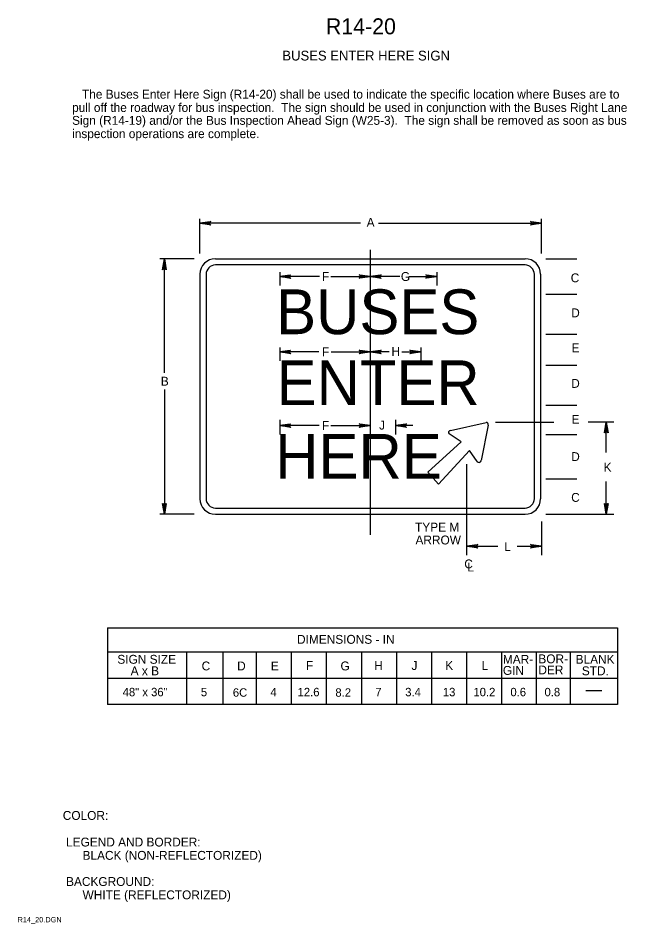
# Model space of a CAD drawing. Extents: x 0.013 to 0.184, y 0.004 to 0.259.
import ezdxf

# ---------------------------------------------------------------- set-up
doc = ezdxf.new("R2010")
doc.units = 0
for name, color, linetype in [('1', 7, 'Continuous'), ('11', 7, 'Continuous'), ('12', 7, 'Continuous'), ('3', 7, 'Continuous')]:
    doc.layers.add(name, color=color, linetype=linetype)

# ---------------------------------------------------------------- blocks, each defined once
blk = doc.blocks.new('RARROW')
at = {"layer": '3'}
for p, q in [((-2.156, 0.28500000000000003), (-2.2665, 0.384625)), ((-2.2665, 0.384625), (0, 0)), ((0, 0), (-2.2665, -0.379125)), ((-2.156, 0.28500000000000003), (-2.075625, 0.12075)), ((0, 0), (-2.156, 0.28500000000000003)), ((-2.14975, -0.2705), (0, 0)), ((-2.075625, 0.12075), (0, 0)), ((0, 0), (-2.074, -0.108)), ((-2.2665, -0.379125), (-2.14975, -0.2705)), ((-2.074, -0.108), (-2.14975, -0.2705))]:
    blk.add_line(p, q, dxfattribs=at)

msp = doc.modelspace()

# ---------------------------------------------------------------- linework, layer by layer
at = {"layer": '11'}
for p, q in [((0.068125, 0.19137500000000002), (0.155375, 0.19137500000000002)), ((0.06375, 0.187), (0.06375, 0.12375)), ((0.15975, 0.187), (0.15975, 0.12375)), ((0.068125, 0.11937500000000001), (0.155375, 0.11937500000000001))]:
    msp.add_line(p, q, dxfattribs=at)
for centre, radius, start, end in [((0.06812500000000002, 0.187), 0.004375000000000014, 90, 180), ((0.155375, 0.187), 0.004375, 0, 90), ((0.06812500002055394, 0.12375000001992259), 0.004375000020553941, 180, 270), ((0.15537499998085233, 0.12375000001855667), 0.004375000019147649, 270, 0)]:
    msp.add_arc(centre, radius, start, end, dxfattribs=at)
at = {"layer": '12'}
for p, q in [((0.134375, 0.14300000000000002), (0.144375, 0.14525)), ((0.145, 0.1445), (0.14300000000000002, 0.1345)), ((0.137375, 0.13975), (0.134, 0.14200000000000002)), ((0.128, 0.13125), (0.137375, 0.13975)), ((0.13975, 0.137375), (0.131, 0.12787500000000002)), ((0.141875, 0.13425), (0.13975, 0.137375)), ((0.131, 0.12787500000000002), (0.128, 0.13125))]:
    msp.add_line(p, q, dxfattribs=at)
for centre, radius, start, end in [((0.13439297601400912, 0.1424246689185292), 0.0005785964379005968, 92.27580833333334, 227.2197416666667), ((0.14444154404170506, 0.14467003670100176), 0.0005837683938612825, 343.06573888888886, 96.5454), ((0.14238124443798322, 0.134570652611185), 0.0005992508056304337, 212.34995833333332, 347.29389444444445)]:
    msp.add_arc(centre, radius, start, end, dxfattribs=at)
at = {"layer": '3'}
for p, q in [((0.06375, 0.192875), (0.06375, 0.202625)), ((0.16, 0.192875), (0.16, 0.202625)), ((0.109, 0.201375), (0.06375, 0.201375)), ((0.114125, 0.201375), (0.16, 0.201375)), ((0.11175, 0.193875), (0.11175, 0.113625)), ((0.062125, 0.19137500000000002), (0.0525, 0.19137500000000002)), ((0.05375, 0.15925), (0.05375, 0.19137500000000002)), ((0.155375, 0.18962500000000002), (0.068125, 0.18962500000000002)), ((0.16125, 0.19137500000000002), (0.17, 0.19137500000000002)), ((0.0655, 0.187), (0.0655, 0.12375)), ((0.08625000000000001, 0.18762500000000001), (0.08625000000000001, 0.183875)), ((0.0975, 0.186375), (0.08625000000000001, 0.186375)), ((0.100625, 0.186375), (0.11175, 0.186375)), ((0.120125, 0.186375), (0.11175, 0.186375)), ((0.122625, 0.186375), (0.1305, 0.186375)), ((0.1305, 0.18762500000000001), (0.1305, 0.183875)), ((0.158, 0.12375), (0.158, 0.187)), ((0.16125, 0.181375), (0.17, 0.181375)), ((0.16125, 0.170125), (0.17, 0.170125)), ((0.08625000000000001, 0.166375), (0.08625000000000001, 0.162625)), ((0.126, 0.166375), (0.126, 0.162625)), ((0.09725, 0.165125), (0.08625000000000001, 0.165125)), ((0.10075, 0.165125), (0.11175, 0.165125)), ((0.117125, 0.165125), (0.11175, 0.165125)), ((0.120625, 0.165125), (0.126, 0.165125)), ((0.16125, 0.161375), (0.17, 0.161375)), ((0.05375, 0.1545), (0.05375, 0.11937500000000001)), ((0.16125, 0.150125), (0.17, 0.150125)), ((0.08625000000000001, 0.146), (0.08625000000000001, 0.141875)), ((0.11887500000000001, 0.146), (0.11887500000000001, 0.141875)), ((0.097375, 0.144375), (0.08625000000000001, 0.144375)), ((0.100625, 0.144375), (0.11175, 0.144375)), ((0.12375, 0.144375), (0.11887500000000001, 0.144375)), ((0.147, 0.145375), (0.1635, 0.145375)), ((0.180375, 0.145375), (0.173125, 0.145375)), ((0.17825, 0.13675), (0.17825, 0.145375)), ((0.16125, 0.141875), (0.17, 0.141875)), ((0.139, 0.107875), (0.139, 0.1335)), ((0.16125, 0.129375), (0.17, 0.129375)), ((0.17825, 0.11937500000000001), (0.17825, 0.128625)), ((0.068125, 0.121125), (0.155375, 0.121125)), ((0.062125, 0.11937500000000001), (0.0525, 0.11937500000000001)), ((0.16125, 0.11937500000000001), (0.180375, 0.11937500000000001)), ((0.16, 0.11737500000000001), (0.16, 0.107875)), ((0.139, 0.110375), (0.14775, 0.110375)), ((0.153125, 0.110375), (0.16, 0.110375)), ((0.03775, 0.08737500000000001), (0.03775, 0.06575)), ((0.03776479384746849, 0.08737500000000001), (0.1813897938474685, 0.08737500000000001)), ((0.181375, 0.08737500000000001), (0.181375, 0.06575)), ((0.181375, 0.0805), (0.03775, 0.0805)), ((0.06001479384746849, 0.0805), (0.06001479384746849, 0.06575)), ((0.07025, 0.0805), (0.07025, 0.06575)), ((0.079625, 0.0805), (0.079625, 0.06575)), ((0.0895, 0.0805), (0.0895, 0.06575)), ((0.099375, 0.0805), (0.099375, 0.06575)), ((0.10925, 0.0805), (0.10925, 0.06575)), ((0.11912500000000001, 0.0805), (0.11912500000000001, 0.06575)), ((0.129, 0.0805), (0.129, 0.06575)), ((0.138875, 0.0805), (0.138875, 0.06575)), ((0.1487647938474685, 0.0805), (0.1487647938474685, 0.06575)), ((0.1585147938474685, 0.0805), (0.1585147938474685, 0.06575)), ((0.168125, 0.0805), (0.168125, 0.06575)), ((0.181375, 0.073125), (0.03775, 0.073125)), ((0.1725363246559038, 0.06971489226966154), (0.17703544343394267, 0.06971489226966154)), ((0.181375, 0.06575), (0.03775, 0.06575))]:
    msp.add_line(p, q, dxfattribs=at)
for centre, radius, start, end in [((0.068125, 0.187), 0.002625, 90, 180), ((0.155375, 0.187), 0.002625, 0, 90), ((0.06812500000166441, 0.12375000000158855), 0.0026250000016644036, 180, 270), ((0.15537499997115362, 0.12375000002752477), 0.0026250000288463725, 270, 0)]:
    msp.add_arc(centre, radius, start, end, dxfattribs=at)

# ---------------------------------------------------------------- block references
at = {"layer": '3', "xscale": 0.0013566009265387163, "yscale": 0.0013419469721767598}
for p, rotation in [((0.06375, 0.201375), 180), ((0.05375, 0.19137500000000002), 90), ((0.08625000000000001, 0.186375), 180), ((0.11175, 0.186375), 180), ((0.08625000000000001, 0.165125), 180), ((0.11175, 0.165125), 180), ((0.08625000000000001, 0.144375), 180), ((0.11887500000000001, 0.144375), 180), ((0.17825, 0.145375), 90), ((0.05375, 0.11937500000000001), -90), ((0.17825, 0.11937500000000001), -90), ((0.139, 0.110375), 180)]:
    msp.add_blockref('RARROW', p, dxfattribs=dict(at, rotation=rotation))
for p in [(0.16, 0.201375), (0.11175, 0.186375), (0.1305, 0.186375), (0.11175, 0.165125), (0.126, 0.165125), (0.11175, 0.144375), (0.16, 0.110375)]:
    msp.add_blockref('RARROW', p, dxfattribs=at)

# ---------------------------------------------------------------- texts
at = {"layer": '1'}
for s, height, p in [('R14-20', 0.0045000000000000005, (0.09925, 0.254625)), ('BUSES ENTER HERE SIGN', 0.00275025, (0.08700000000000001, 0.24725)), ('   The Buses Enter Here Sign (R14-20) shall be used to indicate the specific location where Buses are to', 0.0024997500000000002, (0.02775, 0.23650000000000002)), ('pull off the roadway for bus inspection.  The sign should be used in conjunction with the Buses Right Lane', 0.0024997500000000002, (0.02775, 0.23275)), ('Sign (R14-19) and/or the Bus Inspection Ahead Sign (W25-3).  The sign shall be removed as soon as bus', 0.0024997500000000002, (0.02775, 0.229125)), ('inspection operations are complete.', 0.0024997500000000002, (0.02775, 0.225375)), ('COLOR:', 0.0024997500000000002, (0.025125, 0.03325)), (' LEGEND AND BORDER:', 0.0024997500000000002, (0.025125, 0.025750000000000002)), ('      BLACK (NON-REFLECTORIZED)', 0.0024997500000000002, (0.025125, 0.022)), (' BACKGROUND:', 0.0024997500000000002, (0.025125, 0.014625)), ('      WHITE (REFLECTORIZED)', 0.0024997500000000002, (0.025125, 0.010875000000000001)), ('R14_20.DGN', 0.0015, (0.012375, 0.004375))]:
    msp.add_text(s, height=height, dxfattribs=at).set_placement(p)
at = {"layer": '12'}
for s, p in [('BUSES', (0.08525, 0.170125)), ('ENTER', (0.085375, 0.150125)), ('HERE', (0.085, 0.129375))]:
    msp.add_text(s, height=0.01262475, dxfattribs=at).set_placement(p)
at = {"layer": '3'}
for s, height, p in [('A', 0.0024997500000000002, (0.11075, 0.200375)), ('F', 0.0024997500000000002, (0.098125, 0.185125)), ('G', 0.0024997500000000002, (0.120375, 0.185125)), ('C', 0.0024997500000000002, (0.16825, 0.18475)), ('D', 0.0024997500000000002, (0.168375, 0.174875)), ('F', 0.0024997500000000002, (0.098125, 0.163875)), ('H', 0.0024997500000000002, (0.11775000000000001, 0.164)), ('E', 0.0024997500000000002, (0.1685, 0.165)), ('B', 0.0024997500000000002, (0.05275, 0.155625)), ('D', 0.0024997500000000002, (0.168375, 0.155)), ('F', 0.0024997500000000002, (0.098125, 0.143125)), ('J', 0.0024997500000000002, (0.11425, 0.14325000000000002)), ('E', 0.0024997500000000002, (0.1685, 0.144875)), ('D', 0.0024997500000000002, (0.168375, 0.134375)), ('K', 0.0024997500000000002, (0.1775, 0.131375)), ('C', 0.0024997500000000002, (0.168375, 0.122875)), ('TYPE M', 0.0024997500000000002, (0.124375, 0.1145)), ('ARROW', 0.0024997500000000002, (0.1245, 0.110875)), ('L', 0.0024997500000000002, (0.1495, 0.109)), ('C', 0.0024997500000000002, (0.13825, 0.104125)), ('L', 0.0024997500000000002, (0.139125, 0.10325000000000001)), ('DIMENSIONS - IN', 0.0024997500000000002, (0.091125, 0.082875)), ('SIGN SIZE', 0.0024997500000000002, (0.0405, 0.07725)), ('MAR-', 0.0024997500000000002, (0.149125, 0.07725)), ('BOR-', 0.0024997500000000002, (0.15912500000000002, 0.077375)), ('BLANK', 0.0024997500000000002, (0.169625, 0.07725)), ('C', 0.0024997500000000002, (0.06425, 0.075375)), ('D', 0.0024997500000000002, (0.07425, 0.075375)), ('E', 0.0024997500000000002, (0.08375, 0.075375)), ('F', 0.0024997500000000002, (0.093625, 0.0755)), ('G', 0.0024997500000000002, (0.10337500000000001, 0.075375)), ('H', 0.0024997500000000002, (0.112875, 0.0755)), ('J', 0.0024997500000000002, (0.123375, 0.0755)), ('K', 0.0024997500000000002, (0.132875, 0.0755)), ('L', 0.0024997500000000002, (0.143125, 0.0755)), ('GIN', 0.0024997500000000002, (0.149125, 0.074125)), ('DER', 0.0024997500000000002, (0.15912500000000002, 0.07425)), ('A x B', 0.0024997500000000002, (0.04425, 0.074)), ('STD.', 0.0024997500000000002, (0.171375, 0.074)), ('48" x 36"', 0.0023752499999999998, (0.041995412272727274, 0.06808265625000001)), ('5', 0.0023752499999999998, (0.06402494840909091, 0.06808265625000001)), ('6C', 0.0023752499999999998, (0.07303957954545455, 0.06795765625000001)), ('4', 0.0023752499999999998, (0.08363555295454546, 0.06808265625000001)), ('12.6', 0.0023752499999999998, (0.09127373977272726, 0.06808265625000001)), ('8.2', 0.0023752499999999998, (0.10191997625, 0.06795765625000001)), ('7', 0.0023752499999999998, (0.11318269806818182, 0.06808265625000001)), ('3.4', 0.0023752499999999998, (0.12160699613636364, 0.06808265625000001)), ('13', 0.0023752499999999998, (0.13221184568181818, 0.06808265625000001)), ('10.2', 0.0023752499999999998, (0.14082520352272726, 0.06808265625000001)), ('0.6', 0.0023752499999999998, (0.1512435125, 0.06808265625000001)), ('0.8', 0.0023752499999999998, (0.16085555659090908, 0.06808265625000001))]:
    msp.add_text(s, height=height, dxfattribs=at).set_placement(p)

doc.saveas('drawing.dxf')
